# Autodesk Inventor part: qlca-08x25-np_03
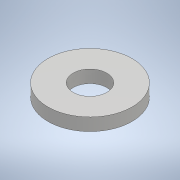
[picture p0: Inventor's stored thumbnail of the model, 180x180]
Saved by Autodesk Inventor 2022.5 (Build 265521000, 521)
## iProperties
Part Number: qlca-08x25-np_03
Material: 一般
Document SubType Name: Modeling
Designer: ImaoCorp
Density: 1 g/cm^3
Appearance: 既定
Author: ImaoCorp
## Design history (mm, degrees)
feature "qlca-08x25-np_03"
node "ソリッド1"
